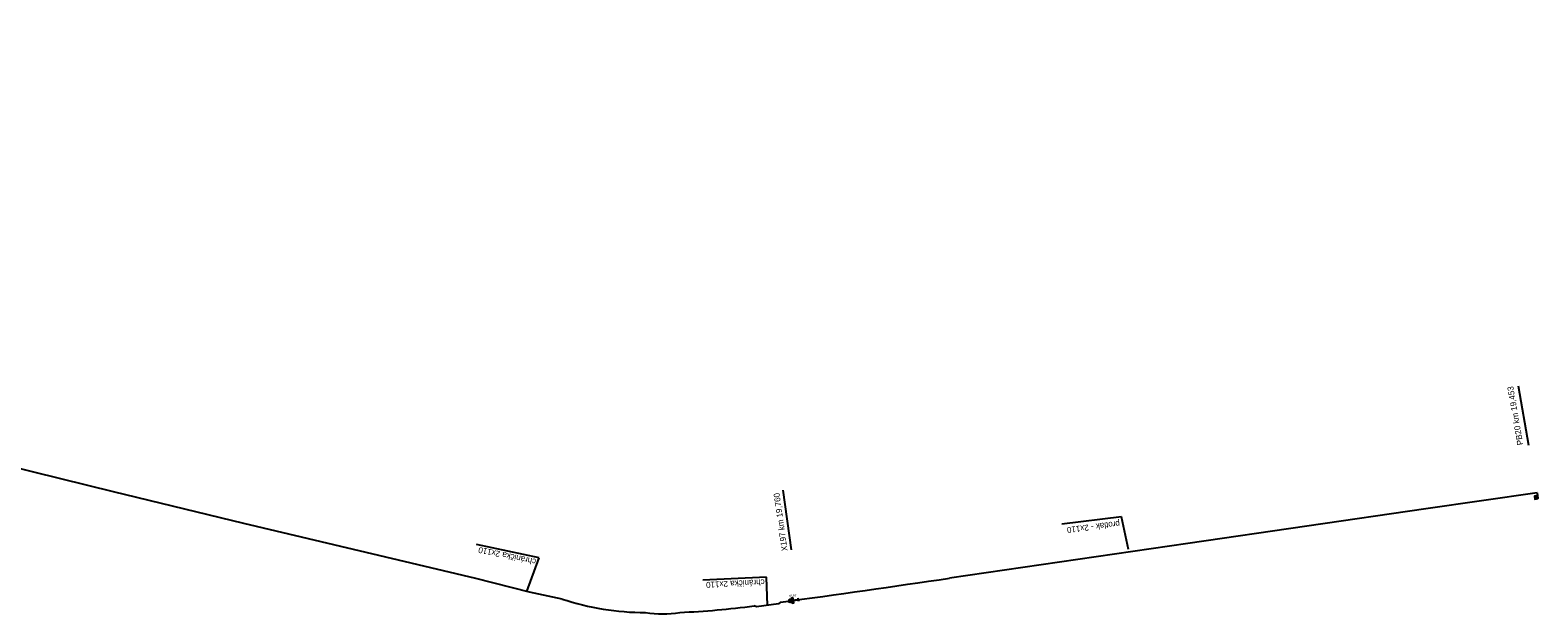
# Model space of a CAD drawing. Extents: x -748315 to -743169, y -1131781 to -1127091.
# Drawn here: x -747520 to -746894, y -1131781 to -1131538 of the extents above; entities that cross this region are included whole.
import ezdxf

# ---------------------------------------------------------------- set-up
doc = ezdxf.new("R2010")
doc.units = 0
for name, color, linetype in [('_Zabezpečovací zařízení', 7, 'Continuous'), ('_Zabezpečovací zařízení_trasa', 7, 'Continuous'), ('Nový stav', 7, 'Continuous')]:
    doc.layers.add(name, color=color, linetype=linetype)

msp = doc.modelspace()

# ---------------------------------------------------------------- linework, layer by layer
at = {"layer": '_Zabezpečovací zařízení'}
for p, q in [((-746895.05, -1131732.78), (-746895.22, -1131731.54)), ((-747201.27, -1131774.66), (-747203.99, -1131775.03)), ((-747201.17, -1131775.34), (-747201.36, -1131773.98))]:
    msp.add_line(p, q, dxfattribs=at)
for points in [[(-746894.6, -1131731.45), (-746895.84, -1131731.62), (-746895.67, -1131732.86), (-746894.43, -1131732.69)], [(-747203.45, -1131773.92), (-747204.13, -1131774.01), (-747203.85, -1131776.05), (-747203.17, -1131775.96)]]:
    msp.add_lwpolyline(points, close=True, dxfattribs=at)
msp.add_lwpolyline([(-746895.22, -1131731.54), (-746895.84, -1131731.62), (-746895.67, -1131732.86), (-746895.05, -1131732.78), (-746895.22, -1131731.54)], dxfattribs=at)
for radius in [0.688, 0.481]:
    msp.add_circle((-747204.67, -1131775.13), radius, dxfattribs=at)
at = {"layer": '_Zabezpečovací zařízení_trasa'}
msp.add_line((-746894.77, -1131730.31), (-746894.43, -1131732.69), dxfattribs=at)
for points in [[(-747299.39, -1131774.36), (-747312.96, -1131771.54), (-747335.19, -1131765.86), (-747431.5, -1131743.03), (-747485.59, -1131729.82), (-747529.87, -1131718.9), (-747616.75, -1131698.31), (-747822.02, -1131648.41), (-747861.48, -1131639.04), (-748013.3, -1131602), (-748116.9, -1131577.08), (-748210.22, -1131554.48), (-748277.3, -1131538.23)], [(-746894.77, -1131730.32), (-746940.94, -1131736.99), (-747039.64, -1131751.37), (-747138.54, -1131765.69)], [(-747208.72, -1131775.69), (-747209.57, -1131776.37), (-747218.69, -1131777.62), (-747219.71, -1131777.21)]]:
    msp.add_lwpolyline(points, dxfattribs=at)
for centre, radius, start, end in [((-748329.43, -1123662.93), 8189.81, 277.865136, 278.361097), ((-747264.33, -1131667.72), 112.26, 251.80149, 269.77384), ((-747265.34, -1131436.61), 343.64, 272.47757, 277.63194), ((-747257.75, -1131734.79), 45.73, 261.16865, 279.14099)]:
    msp.add_arc(centre, radius, start, end, dxfattribs=at)
at = {"layer": 'Nový stav'}
for p, q in [((-746898.23, -1131710.68), (-746902.49, -1131686.04)), ((-747204.19, -1131753.92), (-747207.67, -1131729.16)), ((-747067.19, -1131740.26), (-747092.01, -1131743.28)), ((-747064.32, -1131753.75), (-747067.19, -1131740.26)), ((-747308.93, -1131757.22), (-747334.86, -1131751.66)), ((-747313.94, -1131771.29), (-747308.93, -1131757.22)), ((-747214.48, -1131765.3), (-747240.97, -1131766.59)), ((-747214.13, -1131777), (-747214.48, -1131765.3))]:
    msp.add_line(p, q, dxfattribs=at)

# ---------------------------------------------------------------- texts
at = {"layer": '_Zabezpečovací zařízení'}
msp.add_text('X197', height=1, rotation=7.78933, dxfattribs=at).set_placement((-747205.22, -1131773.71))
at = {"layer": 'Nový stav'}
for s, rotation, p in [('PB20 km 19,453', 99.81338, (-746900.47, -1131710.26)), ('X197 km 19,760', 98.01945, (-747205.77, -1131754.3)), ('protlak - 2x110', 186.93143, (-747068.03, -1131741.87)), ('chránička 2x110', 167.89857, (-747309.99, -1131757.78)), ('chránička 2x110', 182.77856, (-747215.36, -1131766.12))]:
    msp.add_text(s, height=2.5, rotation=rotation, dxfattribs=at).set_placement(p)

doc.saveas('drawing.dxf')
